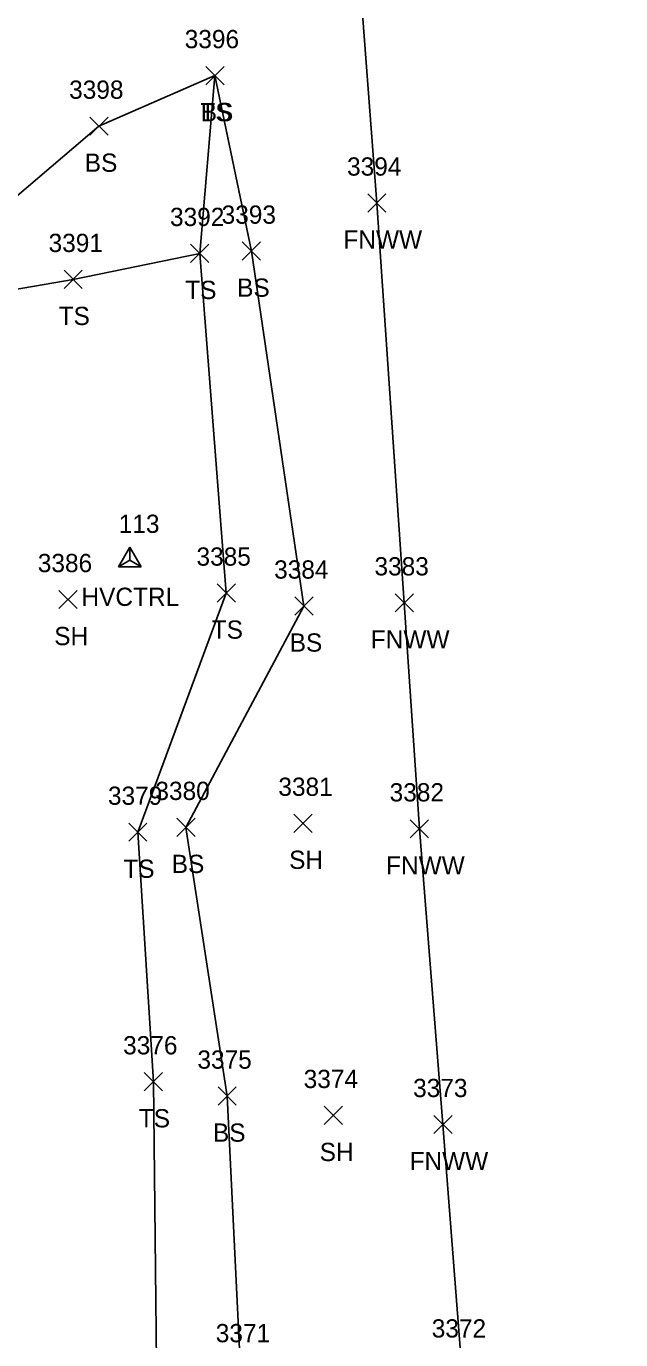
# Model space of a CAD drawing. Extents: x 1650221 to 1650634, y 244606 to 249996.
# Drawn here: x 1650438 to 1650503.1, y 246477.6 to 246621.5 of the extents above; entities that cross this region are included whole.
import ezdxf

# ---------------------------------------------------------------- set-up
doc = ezdxf.new("R2010")
doc.units = 0
for name, color, linetype in [('C_A', 7, 'Continuous'), ('C_I', 7, 'Continuous'), ('CPSM', 7, 'Continuous'), ('L_A', 7, 'Continuous'), ('L_I', 7, 'Continuous'), ('L_TIC', 7, 'Continuous'), ('LELB', 7, 'Continuous'), ('LFNC', 7, 'Continuous'), ('LSOGP', 7, 'Continuous')]:
    doc.layers.add(name, color=color, linetype=linetype)

msp = doc.modelspace()

# ---------------------------------------------------------------- linework, layer by layer
at = {"layer": 'CPSM'}
for p, q in [((1650448.09, 246562.24), (1650449.34, 246564.4)), ((1650450.59, 246562.24), (1650449.34, 246564.4)), ((1650449.35, 246562.96), (1650449.34, 246564.4)), ((1650448.09, 246562.24), (1650449.35, 246562.96)), ((1650448.09, 246562.24), (1650450.59, 246562.24)), ((1650449.35, 246562.96), (1650449.35, 246562.96)), ((1650449.35, 246562.96), (1650450.59, 246562.24))]:
    msp.add_line(p, q, dxfattribs=at)
at = {"layer": 'L_TIC'}
for points in [[(1650457.65, 246615.06), (1650459.65, 246617.06)], [(1650459.65, 246615.06), (1650457.65, 246617.06)], [(1650457.65, 246615.06), (1650459.65, 246617.06)], [(1650459.65, 246615.06), (1650457.65, 246617.06)], [(1650444.95, 246609.52), (1650446.95, 246611.52)], [(1650446.95, 246609.52), (1650444.95, 246611.52)], [(1650475.37, 246601.1), (1650477.37, 246603.1)], [(1650477.37, 246601.1), (1650475.37, 246603.1)], [(1650455.99, 246595.58), (1650457.99, 246597.58)], [(1650457.99, 246595.58), (1650455.99, 246597.58)], [(1650455.99, 246595.58), (1650457.99, 246597.58)], [(1650457.99, 246595.58), (1650455.99, 246597.58)], [(1650461.64, 246595.83), (1650463.64, 246597.83)], [(1650463.64, 246595.83), (1650461.64, 246597.83)], [(1650442.13, 246592.73), (1650444.13, 246594.73)], [(1650444.13, 246592.73), (1650442.13, 246594.73)], [(1650441.58, 246557.66), (1650443.58, 246559.66)], [(1650443.58, 246557.66), (1650441.58, 246559.66)], [(1650458.89, 246558.37), (1650460.89, 246560.37)], [(1650460.89, 246558.37), (1650458.89, 246560.37)], [(1650478.37, 246557.3), (1650480.37, 246559.3)], [(1650480.37, 246557.3), (1650478.37, 246559.3)], [(1650467.39, 246556.95), (1650469.39, 246558.95)], [(1650469.39, 246556.95), (1650467.39, 246558.95)], [(1650454.48, 246532.7), (1650456.48, 246534.7)], [(1650456.48, 246532.7), (1650454.48, 246534.7)], [(1650467.28, 246533.15), (1650469.28, 246535.15)], [(1650469.28, 246533.15), (1650467.28, 246535.15)], [(1650449.21, 246532.17), (1650451.21, 246534.17)], [(1650451.21, 246532.17), (1650449.21, 246534.17)], [(1650480.03, 246532.54), (1650482.03, 246534.54)], [(1650482.03, 246532.54), (1650480.03, 246534.54)], [(1650450.91, 246504.83), (1650452.91, 246506.83)], [(1650452.91, 246504.83), (1650450.91, 246506.83)], [(1650458.99, 246503.26), (1650460.99, 246505.26)], [(1650460.99, 246503.26), (1650458.99, 246505.26)], [(1650470.62, 246501.14), (1650472.62, 246503.14)], [(1650472.62, 246501.14), (1650470.62, 246503.14)], [(1650482.6, 246500.15), (1650484.6, 246502.15)], [(1650484.6, 246500.15), (1650482.6, 246502.15)]]:
    msp.add_lwpolyline(points, dxfattribs=at)
at = {"layer": 'LELB'}
for points in [[(1650479.19, 246312.48), (1650486.78, 246343.04), (1650484.86, 246368.89), (1650480.94, 246392.32), (1650477.18, 246421.11), (1650468.88, 246443.02), (1650461.43, 246474.29), (1650459.99, 246504.26), (1650455.48, 246533.7), (1650468.39, 246557.95), (1650462.64, 246596.83), (1650458.65, 246616.06), (1650445.95, 246610.52), (1650432.73, 246599.27), (1650420.88, 246596.79), (1650423.87, 246613.47), (1650428.27, 246642.15), (1650440.67, 246654.81), (1650470.88, 246672.08), (1650450.6, 246689.53), (1650437.54, 246708.06), (1650451.69, 246713.27), (1650467.72, 246712.4)], [(1650479.19, 246312.48), (1650478.72, 246341.58), (1650480.51, 246366.06), (1650476.32, 246392.29), (1650469.92, 246418.18), (1650461.39, 246442.98), (1650452.29, 246471.6), (1650451.91, 246505.83), (1650450.21, 246533.17), (1650459.89, 246559.37), (1650456.99, 246596.58), (1650458.65, 246616.06)], [(1650411.43, 246590.25), (1650424.68, 246590.56), (1650443.13, 246593.73), (1650456.99, 246596.58)]]:
    msp.add_lwpolyline(points, dxfattribs=at)
at = {"layer": 'LFNC'}
msp.add_lwpolyline([(1650503.06, 246228.04), (1650500.95, 246260.24), (1650499.52, 246280.97), (1650496.75, 246319.42), (1650494.71, 246343.47), (1650493.4, 246369.97), (1650491.44, 246391.35), (1650489.38, 246422.28), (1650487.8, 246445.43), (1650485.64, 246474.81), (1650483.6, 246501.15), (1650481.03, 246533.54), (1650479.37, 246558.3), (1650476.37, 246602.1), (1650473.83, 246635.82)], dxfattribs=at)
at = {"layer": 'LSOGP'}
msp.add_lwpolyline([(1650503.06, 246228.04), (1650500.95, 246260.24), (1650499.52, 246280.97), (1650496.75, 246319.42), (1650494.71, 246343.47), (1650493.4, 246369.97), (1650491.44, 246391.35), (1650489.38, 246422.28), (1650487.8, 246445.43), (1650485.64, 246474.81), (1650483.6, 246501.15), (1650481.03, 246533.54), (1650479.37, 246558.3), (1650476.37, 246602.1), (1650473.83, 246635.82)], dxfattribs=at)

# ---------------------------------------------------------------- texts
at = {"layer": 'C_A'}
msp.add_text('HVCTRL', height=2, dxfattribs=at).set_placement((1650444.04, 246557.96))
at = {"layer": 'C_I'}
msp.add_text('113', height=2, dxfattribs=at).set_placement((1650448.12, 246565.96))
at = {"layer": 'L_A'}
for s, p in [('TS', (1650457.06, 246611.06)), ('BS', (1650457.09, 246611.06)), ('BS', (1650444.4, 246605.52)), ('FNWW', (1650472.71, 246597.1)), ('BS', (1650461.08, 246591.83)), ('TS', (1650455.4, 246591.58)), ('TS', (1650455.4, 246591.58)), ('TS', (1650441.54, 246588.73)), ('TS', (1650458.3, 246554.37)), ('SH', (1650441.06, 246553.66)), ('BS', (1650466.83, 246552.95)), ('FNWW', (1650475.71, 246553.3)), ('BS', (1650453.92, 246528.7)), ('SH', (1650466.77, 246529.15)), ('FNWW', (1650477.38, 246528.54)), ('TS', (1650448.62, 246528.17)), ('TS', (1650450.32, 246500.83)), ('BS', (1650458.43, 246499.26)), ('SH', (1650470.11, 246497.14)), ('FNWW', (1650479.95, 246496.15))]:
    msp.add_text(s, height=2, dxfattribs=at).set_placement(p)
at = {"layer": 'L_I'}
for s, p in [('3396', (1650455.34, 246619.06)), ('3396', (1650455.34, 246619.06)), ('3398', (1650442.69, 246613.52)), ('3394', (1650473.11, 246605.1)), ('3392', (1650453.73, 246599.58)), ('3392', (1650453.73, 246599.58)), ('3393', (1650459.38, 246599.83)), ('3391', (1650440.44, 246596.73)), ('3386', (1650439.26, 246561.66)), ('3385', (1650456.63, 246562.37)), ('3384', (1650465.13, 246560.95)), ('3383', (1650476.11, 246561.3)), ('3381', (1650465.59, 246537.15)), ('3379', (1650446.94, 246536.17)), ('3380', (1650452.13, 246536.7)), ('3382', (1650477.77, 246536.54)), ('3376', (1650448.6, 246508.83)), ('3375', (1650456.73, 246507.26)), ('3374', (1650468.36, 246505.14)), ('3373', (1650480.34, 246504.15)), ('3371', (1650458.74, 246477.29)), ('3372', (1650482.38, 246477.81))]:
    msp.add_text(s, height=2, dxfattribs=at).set_placement(p)

doc.saveas('drawing.dxf')
